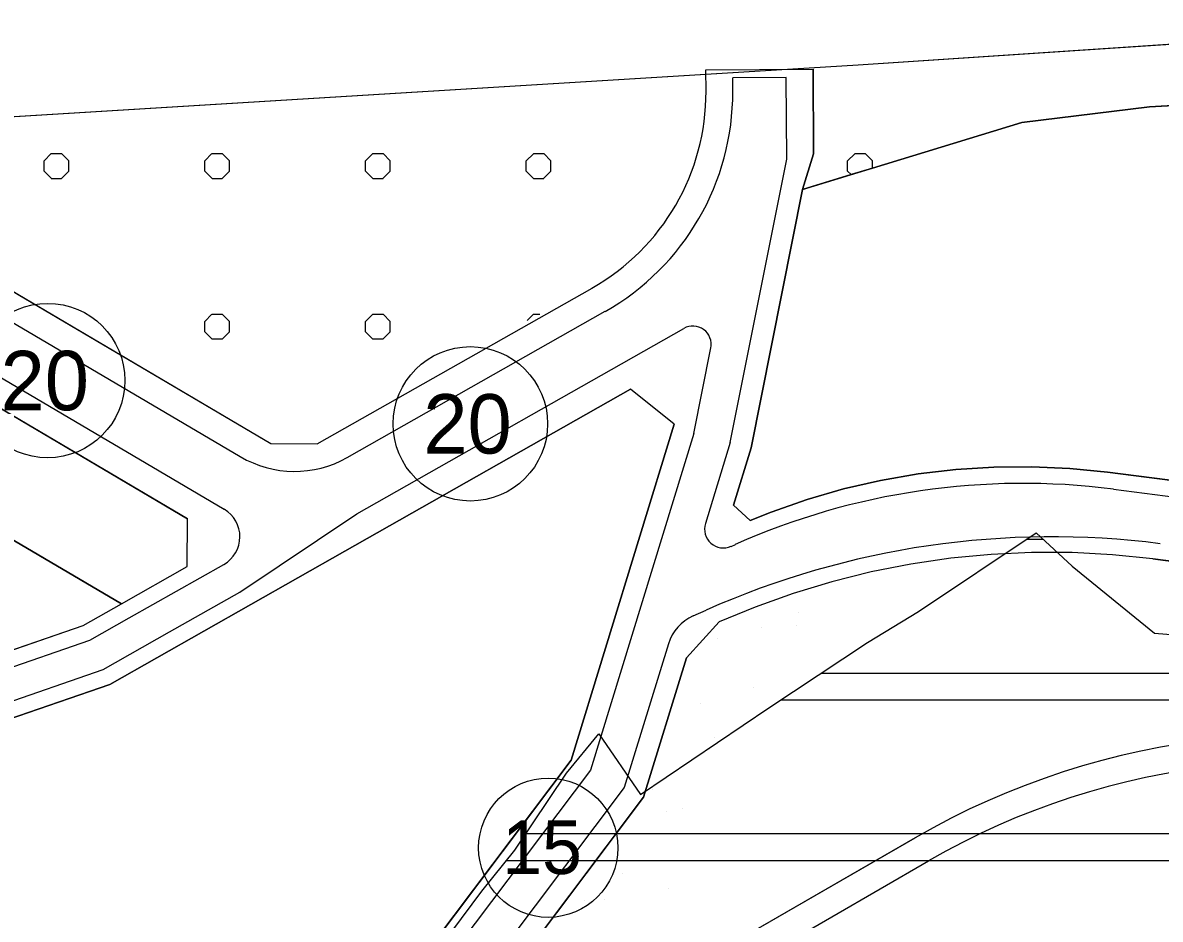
# Model space of a CAD drawing. Extents: x 427903 to 430077, y 4477233 to 4480385.
# Drawn here: x 428396.6 to 428608.9, y 4479035 to 4479202.5 of the extents above; entities that cross this region are included whole.
import ezdxf

# ---------------------------------------------------------------- set-up
doc = ezdxf.new("R2010")
doc.units = 0
for name, color, linetype in [('ADAKENARI', 7, 'Continuous'), ('KALDIRIM', 7, 'Continuous'), ('KALDIRIM2', 7, 'Continuous'), ('PL_AYA_BOLGE_PARKI', 7, 'Continuous'), ('PL_KA_TARIM_OZEL', 7, 'Continuous'), ('PL_KON_ONE_100', 7, 'Continuous'), ('PL_TICARET', 7, 'Continuous'), ('rezerv yapı alan', 7, 'Continuous'), ('SIT_1_DER_ARKEOLOJIK', 7, 'Continuous'), ('SM_DAIRE', 7, 'Continuous'), ('SM_YGEN', 7, 'Continuous'), ('TR_2_SITKORUMA', 7, 'Continuous'), ('TR_AZYOGUNKONUT', 7, 'Continuous'), ('TR_OZELMAHSUL', 7, 'Continuous'), ('TR_PARKALANI', 7, 'Continuous'), ('TR_TALIISMERK', 7, 'Continuous')]:
    doc.layers.add(name, color=color, linetype=linetype)

msp = doc.modelspace()

# ---------------------------------------------------------------- linework, layer by layer
at = {"layer": 'ADAKENARI'}
for p, q in [((428524.09, 4479193.68), (428544.09, 4479193.78)), ((428524.11, 4479189.65), (428524.09, 4479193.68)), ((428544.17, 4479177.97), (428544.09, 4479193.78)), ((428606.92, 4479186.76), (428654.88, 4479189.48)), ((428583.07, 4479183.82), (428606.92, 4479186.76)), ((428542.13, 4479171.31), (428583.07, 4479183.82)), ((428542.13, 4479171.31), (428544.17, 4479177.97)), ((428532.53, 4479123.05), (428542.13, 4479171.31)), ((428363.07, 4479170.92), (428442.85, 4479123.88)), ((428451.51, 4479123.8), (428502.83, 4479152.9)), ((428369.81, 4479143.72), (428427.34, 4479109.8)), ((428336.42, 4479140.19), (428414.97, 4479093.88)), ((428456.71, 4479103.76), (428510.04, 4479134)), ((428518.19, 4479127.46), (428510.04, 4479134)), ((428518.19, 4479127.46), (428498.91, 4479064.71)), ((428442.85, 4479123.88), (428451.51, 4479123.8)), ((428529.23, 4479112.32), (428532.53, 4479123.05)), ((428570.75, 4479119.02), (428563.7, 4479118.19)), ((428577.82, 4479119.47), (428570.75, 4479119.02)), ((428584.92, 4479119.53), (428577.82, 4479119.47)), ((428592, 4479119.21), (428584.92, 4479119.53)), ((428599.06, 4479118.5), (428592, 4479119.21)), ((428896.47, 4479080.34), (428599.06, 4479118.5)), ((428556.71, 4479116.97), (428549.8, 4479115.37)), ((428563.7, 4479118.19), (428556.71, 4479116.97)), ((428549.8, 4479115.37), (428542.99, 4479113.4)), ((428532.38, 4479109.45), (428529.23, 4479112.32)), ((428542.99, 4479113.4), (428536.29, 4479111.06)), ((428427.27, 4479100.86), (428427.34, 4479109.8)), ((428536.29, 4479111.06), (428532.38, 4479109.45)), ((428412.82, 4479078.87), (428456.71, 4479103.76)), ((428584.89, 4479103.5), (428577.34, 4479103.15)), ((428592.44, 4479103.47), (428584.89, 4479103.5)), ((428599.98, 4479103.07), (428592.44, 4479103.47)), ((428562.35, 4479101.34), (428554.94, 4479099.87)), ((428569.82, 4479102.43), (428562.35, 4479101.34)), ((428577.34, 4479103.15), (428569.82, 4479102.43)), ((428607.5, 4479102.3), (428599.98, 4479103.07)), ((428607.5, 4479102.3), (428760.51, 4479082.67)), ((428414.97, 4479093.88), (428427.27, 4479100.86)), ((428554.94, 4479099.87), (428547.61, 4479098.04)), ((428547.61, 4479098.04), (428540.38, 4479095.85)), ((428540.38, 4479095.85), (428533.27, 4479093.31)), ((428407.87, 4479089.86), (428414.97, 4479093.88)), ((428533.27, 4479093.31), (428526.56, 4479090.52)), ((428334.22, 4479064.44), (428407.87, 4479089.86)), ((428520.47, 4479083.83), (428526.56, 4479090.52)), ((428512.47, 4479057.79), (428520.47, 4479083.83)), ((428337.6, 4479052.91), (428412.82, 4479078.87)), ((428498.91, 4479064.71), (428466.09, 4479021.09)), ((428474.66, 4479007.54), (428512.47, 4479057.79)), ((428563.16, 4479050.23), (428479.52, 4479001.93))]:
    msp.add_line(p, q, dxfattribs=at)
for centre, radius, start, end in [((428482.11, 4479189.43), 42, 299.5543, 0.2965), ((428635.16, 4478925.53), 143.99, 24.1086, 120.0039)]:
    msp.add_arc(centre, radius, start, end, dxfattribs=at)
at = {"layer": 'KALDIRIM'}
for p, q in [((428600.16, 4479115.34), (428896.09, 4479077.37)), ((428404.46, 4478952.81), (428565.66, 4479045.9))]:
    msp.add_line(p, q, dxfattribs=at)
msp.add_arc((428635.16, 4478925.53), 139, 24.3922, 120.0039, dxfattribs=at)
at = {"layer": 'KALDIRIM2'}
for p, q in [((428539.1, 4479192.23), (428529.1, 4479192.17)), ((428529.11, 4479189.68), (428529.1, 4479192.17)), ((428539.18, 4479176.99), (428539.1, 4479192.23)), ((428528.64, 4479124.03), (428539.18, 4479176.99)), ((428361.03, 4479166.31), (428437.18, 4479121.41)), ((428457.14, 4479121.25), (428505.3, 4479148.55)), ((428373.43, 4479147.39), (428434.19, 4479111.57)), ((428458.91, 4479110.75), (428519.95, 4479145.36)), ((428521.85, 4479125.75), (428525.02, 4479141.7)), ((428521.85, 4479125.75), (428502.52, 4479062.86)), ((428528.64, 4479124.03), (428523.99, 4479108.9)), ((428437.06, 4479096.07), (428458.91, 4479110.75)), ((428528.79, 4479104.65), (428529.59, 4479105.01)), ((428416.44, 4479091.27), (428434.1, 4479101.28)), ((428423.97, 4479088.65), (428437.06, 4479096.07)), ((428521.71, 4479091.66), (428524.13, 4479092.73)), ((428409.11, 4479087.11), (428416.44, 4479091.27)), ((428411.58, 4479081.62), (428423.97, 4479088.65)), ((428335.06, 4479061.56), (428409.11, 4479087.11)), ((428517.1, 4479086.45), (428508.85, 4479059.63)), ((428336.75, 4479055.8), (428411.58, 4479081.62)), ((428502.52, 4479062.86), (428469.28, 4479018.69)), ((428508.85, 4479059.63), (428474.88, 4479014.48))]:
    msp.add_line(p, q, dxfattribs=at)
for centre, radius, start, end in [((428482.11, 4479189.43), 47, 299.5543, 0.2965), ((428521.65, 4479142.37), 3.44, 348.7508, 119.5543), ((428447.31, 4479138.59), 19.94, 239.4784, 299.5543), ((428583.32, 4478984.1), 132.31, 82.689, 113.9627), ((428431.17, 4479106.45), 5.94, 299.5543, 59.4784), ((428527.36, 4479107.87), 3.52, 162.9188, 293.9627), ((428588.68, 4478947.51), 158.92, 82.689, 113.9627), ((428525.12, 4479083.99), 8.4, 113.9627, 162.9188)]:
    msp.add_arc(centre, radius, start, end, dxfattribs=at)
at = {"layer": 'PL_AYA_BOLGE_PARKI'}
for points in [[(428900.92, 4479004.53), (428894.56, 4479065.47), (428760.51, 4479082.67), (428607.5, 4479102.3), (428599.98, 4479103.07), (428592.44, 4479103.47), (428584.89, 4479103.5), (428577.34, 4479103.15), (428569.82, 4479102.43), (428562.35, 4479101.34), (428554.94, 4479099.87), (428547.61, 4479098.04), (428540.38, 4479095.85), (428533.27, 4479093.31), (428526.56, 4479090.52), (428520.47, 4479083.83), (428512.47, 4479057.79), (428474.66, 4479007.54), (428479.52, 4479001.93)], [(428479.52, 4479001.93), (428563.16, 4479050.23)]]:
    msp.add_lwpolyline(points, dxfattribs=at)
msp.add_arc((428635.16, 4478925.53), 143.99, 24.1086, 120.0039, dxfattribs=at)
at = {"layer": 'PL_KA_TARIM_OZEL'}
for points in [[(428203.74, 4479325.99), (428181.54, 4479286.96), (428161.9, 4479277.22), (428155.71, 4479277.28), (428133.74, 4479244.08), (428133.03, 4479242.09), (428363.07, 4479170.92), (428442.85, 4479123.88), (428451.51, 4479123.8), (428502.83, 4479152.9)], [(428524.11, 4479189.65), (428524.09, 4479193.68), (428544.09, 4479193.78), (428544.17, 4479177.97), (428542.13, 4479171.31), (428551.2, 4479174.09), (428555.17, 4479175.3), (428583.07, 4479183.82), (428606.92, 4479186.76), (428654.88, 4479189.48), (428679.34, 4479188.24), (428704.57, 4479183.24), (428730.39, 4479176.15), (428730.55, 4479176.1), (428735.12, 4479174.7), (428756.92, 4479167.99), (428785.09, 4479158.64), (428817.55, 4479146.71), (428820.54, 4479145.48), (428824.34, 4479143.92), (428857.92, 4479130.08)]]:
    msp.add_lwpolyline(points, dxfattribs=at)
msp.add_arc((428482.11, 4479189.43), 42, 299.5543, 0.2965, dxfattribs=at)
at = {"layer": 'PL_KON_ONE_100'}
for points in [[(428654.88, 4479189.48), (428606.92, 4479186.76), (428583.07, 4479183.82), (428555.17, 4479175.3), (428551.2, 4479174.09), (428542.13, 4479171.31), (428532.53, 4479123.05), (428529.23, 4479112.32), (428532.38, 4479109.45), (428536.29, 4479111.06), (428542.99, 4479113.4), (428549.8, 4479115.37), (428556.71, 4479116.97), (428563.7, 4479118.19), (428570.75, 4479119.02), (428577.82, 4479119.47), (428584.92, 4479119.53), (428592, 4479119.21), (428599.06, 4479118.5), (428896.47, 4479080.34)], [(428245.6, 4479042.9), (428334.22, 4479064.44), (428407.87, 4479089.86), (428414.97, 4479093.88), (428336.42, 4479140.19), (428162.77, 4479091.94), (428162.26, 4479088.05), (428236.43, 4479044.27), (428245.6, 4479042.9)], [(428412.82, 4479078.87), (428337.6, 4479052.91), (428245.8, 4479030.61), (428161.23, 4479010.05), (428153.73, 4479002.08), (428148.66, 4478973.65), (428150.94, 4478971.76), (428192.16, 4478987.37), (428251.89, 4478986.28), (428264.07, 4478976.56), (428299.56, 4478998.87), (428361.62, 4478962.24), (428466.09, 4479021.09), (428498.91, 4479064.71), (428518.19, 4479127.46), (428510.04, 4479134), (428456.71, 4479103.76), (428412.82, 4479078.87)]]:
    msp.add_lwpolyline(points, dxfattribs=at)
at = {"layer": 'PL_TICARET'}
msp.add_lwpolyline([(428336.42, 4479140.19), (428414.97, 4479093.88), (428427.27, 4479100.86), (428427.34, 4479109.8), (428369.81, 4479143.72), (428355.79, 4479145.57), (428336.42, 4479140.19)], dxfattribs=at)
at = {"layer": 'rezerv yapı alan'}
for p, q in [((428552.54, 4479194.57), (428656.99, 4479201.54)), ((428368.56, 4479183.35), (428552.54, 4479194.57))]:
    msp.add_line(p, q, dxfattribs=at)
msp.add_lwpolyline([(427921.98, 4479290.57), (427971.55, 4479260.72), (427987.38, 4479256.4), (428128.47, 4479257.63), (428368.56, 4479183.35), (428552.54, 4479194.57), (428656.99, 4479201.54), (428694.28, 4479196.96), (428778.69, 4479177.41), (428853.9, 4479147.32), (428942.46, 4479108.55), (429057.71, 4479108.55), (429083.4, 4479100.66), (429102.93, 4479079.75), (429129.55, 4479022.57), (429151, 4479001.12), (429217.97, 4478963.3), (429343.9, 4478891.1), (429611.87, 4478938.66), (429782.06, 4478938.49), (429965.11, 4478882.46), (430027.68, 4478900.91), (430040.04, 4478910.67)], dxfattribs=at)
at = {"layer": 'SIT_1_DER_ARKEOLOJIK'}
msp.add_lwpolyline([(428471.05, 4479025.15), (428482.26, 4479040.24), (428488.4, 4479047.92), (428498.07, 4479062.29), (428504.12, 4479069.61), (428511.89, 4479058.31), (428535.84, 4479074.49), (428554.27, 4479086.68), (428563.76, 4479092.47), (428585.72, 4479107.2), (428592.49, 4479100.96), (428607.85, 4479088.4), (428618.61, 4479087.59), (428660.17, 4479085.33), (428661.98, 4479097.17), (428707.7, 4479096.62), (428720.89, 4479065.81), (428748.81, 4479068.79), (428760.65, 4479064.91), (428790.1, 4479038.16), (428797.87, 4479031.21)], dxfattribs=at)
at = {"layer": 'SM_DAIRE'}
for centre, radius in [((428401.21, 4479135.62), 14.42), ((428480.12, 4479127.53), 14.42), ((428494.66, 4479048.34), 13)]:
    msp.add_circle(centre, radius, dxfattribs=at)
at = {"layer": 'TR_2_SITKORUMA'}
for p, q in [((428583.9, 4479105.98), (428587.04, 4479105.98)), ((428545.64, 4479080.98), (428714.4, 4479080.98)), ((428538.09, 4479075.98), (428716.54, 4479075.98)), ((428490.46, 4479050.98), (428775.99, 4479050.98)), ((428486.84, 4479045.98), (428781.5, 4479045.98))]:
    msp.add_line(p, q, dxfattribs=at)
at = {"layer": 'TR_AZYOGUNKONUT'}
for points in [[(428654.88, 4479189.48), (428606.92, 4479186.76), (428583.07, 4479183.82), (428555.17, 4479175.3), (428551.2, 4479174.09), (428542.13, 4479171.31), (428532.53, 4479123.05), (428529.23, 4479112.32), (428532.38, 4479109.45), (428536.29, 4479111.06), (428542.99, 4479113.4), (428549.8, 4479115.37), (428556.71, 4479116.97), (428563.7, 4479118.19), (428570.75, 4479119.02), (428577.82, 4479119.47), (428584.92, 4479119.53), (428592, 4479119.21), (428599.06, 4479118.5), (428896.47, 4479080.34)], [(428162.26, 4479088.05), (428236.43, 4479044.27), (428245.6, 4479042.9), (428334.22, 4479064.44), (428407.87, 4479089.86), (428414.97, 4479093.88), (428336.42, 4479140.19), (428162.77, 4479091.94), (428162.26, 4479088.05)], [(428456.71, 4479103.76), (428412.82, 4479078.87), (428337.6, 4479052.91), (428245.8, 4479030.61), (428161.23, 4479010.05), (428153.73, 4479002.08), (428148.66, 4478973.65), (428150.94, 4478971.76), (428192.16, 4478987.37), (428251.89, 4478986.28), (428264.07, 4478976.56), (428299.56, 4478998.87), (428361.62, 4478962.24), (428466.09, 4479021.09), (428498.91, 4479064.71), (428518.19, 4479127.46), (428510.04, 4479134), (428456.71, 4479103.76)]]:
    msp.add_lwpolyline(points, dxfattribs=at)
at = {"layer": 'TR_OZELMAHSUL'}
for p, q in [((428400.54, 4479176.65), (428401.89, 4479178.01)), ((428401.9, 4479178.02), (428403.82, 4479178.02)), ((428405.18, 4479176.65), (428403.82, 4479178.01)), ((428430.54, 4479176.65), (428431.89, 4479178.01)), ((428431.9, 4479178.02), (428433.82, 4479178.02)), ((428435.17, 4479176.65), (428433.82, 4479178.01)), ((428460.53, 4479176.65), (428461.89, 4479178.01)), ((428461.9, 4479178.02), (428463.82, 4479178.02)), ((428465.17, 4479176.65), (428463.82, 4479178.01)), ((428490.53, 4479176.65), (428491.89, 4479178)), ((428491.9, 4479178.02), (428493.82, 4479178.02)), ((428495.17, 4479176.65), (428493.82, 4479178.01)), ((428550.53, 4479176.65), (428551.89, 4479178)), ((428550.53, 4479176.65), (428551.89, 4479178)), ((428551.9, 4479178.02), (428553.82, 4479178.02)), ((428555.17, 4479176.65), (428553.82, 4479178.01)), ((428400.54, 4479174.75), (428400.54, 4479176.66)), ((428405.17, 4479174.75), (428405.17, 4479176.66)), ((428430.54, 4479174.75), (428430.54, 4479176.66)), ((428435.17, 4479174.75), (428435.17, 4479176.66)), ((428460.54, 4479174.75), (428460.54, 4479176.66)), ((428465.17, 4479174.75), (428465.17, 4479176.66)), ((428490.54, 4479174.75), (428490.54, 4479176.66)), ((428495.17, 4479174.75), (428495.17, 4479176.66)), ((428550.54, 4479174.75), (428550.54, 4479176.66)), ((428550.54, 4479174.75), (428550.54, 4479176.66)), ((428555.17, 4479175.3), (428555.17, 4479176.66)), ((428401.91, 4479173.38), (428400.55, 4479174.74)), ((428403.81, 4479173.38), (428405.16, 4479174.74)), ((428431.9, 4479173.38), (428430.55, 4479174.74)), ((428433.81, 4479173.38), (428435.16, 4479174.74)), ((428461.9, 4479173.38), (428460.55, 4479174.74)), ((428463.8, 4479173.38), (428465.16, 4479174.74)), ((428491.9, 4479173.38), (428490.55, 4479174.74)), ((428493.8, 4479173.38), (428495.16, 4479174.73)), ((428551.2, 4479174.09), (428550.55, 4479174.74)), ((428551.2, 4479174.09), (428550.55, 4479174.74)), ((428401.9, 4479173.39), (428403.82, 4479173.39)), ((428431.9, 4479173.39), (428433.82, 4479173.39)), ((428461.9, 4479173.39), (428463.82, 4479173.39)), ((428491.9, 4479173.39), (428493.82, 4479173.39)), ((428430.54, 4479146.65), (428431.89, 4479148.01)), ((428431.9, 4479148.02), (428433.82, 4479148.02)), ((428435.17, 4479146.65), (428433.82, 4479148.01)), ((428460.53, 4479146.65), (428461.89, 4479148.01)), ((428461.9, 4479148.02), (428463.82, 4479148.02)), ((428465.17, 4479146.65), (428463.82, 4479148.01)), ((428490.71, 4479146.83), (428491.89, 4479148.01)), ((428491.9, 4479148.02), (428493.08, 4479148.02)), ((428430.54, 4479144.75), (428430.54, 4479146.66)), ((428435.17, 4479144.75), (428435.17, 4479146.66)), ((428460.54, 4479144.75), (428460.54, 4479146.66)), ((428465.17, 4479144.75), (428465.17, 4479146.66)), ((428431.9, 4479143.38), (428430.55, 4479144.74)), ((428433.81, 4479143.38), (428435.16, 4479144.74)), ((428461.9, 4479143.38), (428460.55, 4479144.74)), ((428463.8, 4479143.38), (428465.16, 4479144.74)), ((428431.9, 4479143.39), (428433.82, 4479143.39)), ((428461.9, 4479143.39), (428463.82, 4479143.39))]:
    msp.add_line(p, q, dxfattribs=at)
at = {"layer": 'TR_PARKALANI'}
for p, q in [((428541.35, 4479092.38), (428541.35, 4479092.38)), ((428534.52, 4479089.42), (428534.52, 4479089.42)), ((428534.52, 4479089.42), (428534.52, 4479089.42)), ((428541.01, 4479089.95), (428541.01, 4479089.95)), ((428541.01, 4479089.95), (428541.01, 4479089.95)), ((428526.24, 4479087.35), (428526.24, 4479087.35)), ((428526.24, 4479087.35), (428526.24, 4479087.35)), ((428532.9, 4479078.37), (428532.9, 4479078.37)), ((428532.9, 4479078.37), (428532.9, 4479078.37)), ((428518.12, 4479075.76), (428518.12, 4479075.76)), ((428518.12, 4479075.76), (428518.12, 4479075.76)), ((428523.1, 4479075.29), (428523.1, 4479075.29)), ((428525.63, 4479068.9), (428525.63, 4479068.9)), ((428524.78, 4479066.78), (428524.78, 4479066.78)), ((428524.78, 4479066.78), (428524.78, 4479066.78)), ((428514.14, 4479059.26), (428514.14, 4479059.26)), ((428514.14, 4479059.26), (428514.14, 4479059.26)), ((428516.67, 4479055.2), (428516.67, 4479055.2)), ((428516.67, 4479055.2), (428516.67, 4479055.2)), ((428519.63, 4479055.59), (428519.63, 4479055.59)), ((428508.56, 4479043.62), (428508.56, 4479043.62)), ((428508.56, 4479043.62), (428508.56, 4479043.62)), ((428517.02, 4479040.82), (428517.02, 4479040.82)), ((428501.38, 4479038.5), (428501.38, 4479038.5)), ((428505.25, 4479038.75), (428505.25, 4479038.75))]:
    msp.add_line(p, q, dxfattribs=at)
at = {"layer": 'TR_TALIISMERK'}
msp.add_lwpolyline([(428355.79, 4479145.57), (428336.42, 4479140.19), (428414.97, 4479093.88), (428427.27, 4479100.86), (428427.34, 4479109.8), (428369.81, 4479143.72), (428355.79, 4479145.57)], dxfattribs=at)

# ---------------------------------------------------------------- texts
at = {"layer": 'SM_YGEN'}
for s, height, p in [('20', 11.092, (428392.43, 4479130.07)), ('20', 11.092, (428471.34, 4479121.98)), ('15', 10, (428486.06, 4479043.44))]:
    msp.add_text(s, height=height, rotation=0.0002, dxfattribs=at).set_placement(p)

doc.saveas('drawing.dxf')
